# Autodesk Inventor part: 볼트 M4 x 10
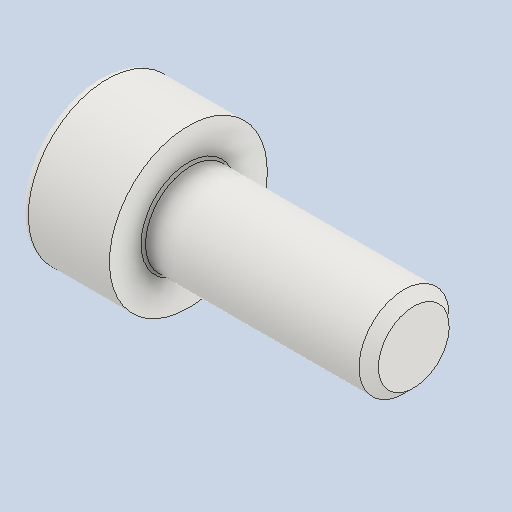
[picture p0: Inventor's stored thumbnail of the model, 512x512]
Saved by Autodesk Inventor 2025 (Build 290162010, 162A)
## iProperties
Created: 2024-07
Part Number: 볼트 M4 x 10
Material: 강철, 연강
Description: 6각머리 태핑 나사
Document SubType Name: Modeling
Designer: 계정
Density: 7.86 g/cm^3
Appearance: 기본값
Author: jhkim
Revision Number: 1
Sending System: Autodesk Inventor 2025
Preprocessor: ST-DEVELOPER v20
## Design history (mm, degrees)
feature "Solid1"
node "솔리드1"
